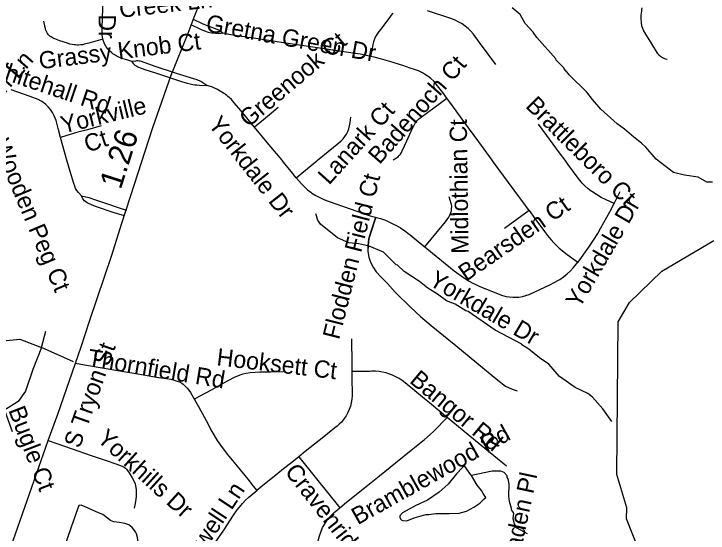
# Model space of a CAD drawing. Extents: x 1383679 to 1536984, y 460658 to 651027.
# Drawn here: x 1424590 to 1428413, y 515011 to 517873 of the extents above; entities that cross this region are included whole.
import ezdxf

# ---------------------------------------------------------------- set-up
doc = ezdxf.new("R2010")
doc.units = 0
for name, color, linetype in [('Exist Hydrographic Creek Single Shore', 7, 'Continuous'), ('Exist Hydrographic Misc Water Feature', 7, 'Continuous'), ('Exist Road Non-System Type 51', 7, 'Continuous'), ('Exist Road Non-System Type 51 Label', 7, 'Continuous'), ('Exist Road Primary NC Label', 7, 'Continuous'), ('Exist Road Primary NC Service Mileage Hundredths English Label', 7, 'Continuous'), ('Exist Road Primary NC UnDivided 4 Lane Attributed', 7, 'Continuous')]:
    doc.layers.add(name, color=color, linetype=linetype)

msp = doc.modelspace()

# ---------------------------------------------------------------- linework, layer by layer
at = {"layer": 'Exist Hydrographic Creek Single Shore'}
msp.add_lwpolyline([(1428455.5, 514657.5), (1428398.5, 514707.9), (1428207.5, 514728.2), (1428083.4, 514789.8), (1427964.5, 515090.9), (1427965.4, 515149.9), (1427910.5, 515334.8), (1427918.5, 516175), (1427979.5, 516282.1), (1428157.5, 516455.7), (1428444.5, 516623.9)], dxfattribs=at)
at = {"layer": 'Exist Hydrographic Misc Water Feature'}
for points in [[(1428438.2, 516945.2), (1428406.2, 516945.9), (1428358.9, 516973), (1428283.1, 516984.7), (1428223.3, 516998), (1428127, 517072.1), (1428070.4, 517137.4), (1428046.9, 517159.9), (1428003.5, 517192.9), (1427952.6, 517238), (1427913.1, 517266.9), (1427822.9, 517346.9), (1427776, 517399.9), (1427745.2, 517440.9), (1427648.9, 517534.7), (1427645.1, 517542.8), (1427619.7, 517569.3), (1427617.7, 517575.4), (1427576.7, 517618.3), (1427574.9, 517624.4), (1427469.4, 517742.7), (1427450, 517771.1), (1427405, 517820.1), (1427378.1, 517868.7), (1427334.8, 517905.6)], [(1427882.2, 515626.6), (1427833, 515695.4), (1427776.4, 515760.6), (1427750.9, 515781.2), (1427681.6, 515814.7), (1427594.9, 515874.6), (1427536.3, 515942), (1427483.9, 515977.1), (1427426.1, 516024.4), (1427386.6, 516049.2), (1427386.7, 516053.2), (1427240.3, 516130.5), (1427092.5, 516231.8), (1427078.6, 516236.1), (1427019.4, 516273.4), (1426971.8, 516290.5), (1426922.5, 516328.1), (1426869.3, 516360.8), (1426824.1, 516397.7), (1426739.3, 516453.7), (1426702, 516488.5), (1426696, 516490.6), (1426625.6, 516560.1), (1426546.2, 516591.9), (1426490.4, 516605.1), (1426434.6, 516610.4), (1426371.2, 516637.8), (1426278.8, 516713.9), (1426263.2, 516736.2), (1426252.1, 516770.5)], [(1427109.6, 515328.1), (1427107, 515331.9), (1427070.8, 515382.3), (1427059.9, 515372.9), (1427027.2, 515337.7), (1426981.8, 515280.7), (1426932.9, 515237.8), (1426867.9, 515193.3), (1426803.2, 515162.8), (1426730.4, 515122.4), (1426716.1, 515106.8), (1426715.8, 515096.8), (1426723.6, 515084.6), (1426731.5, 515080.4), (1426753.5, 515079.9), (1426793.8, 515095), (1426858.2, 515113.5), (1426874.2, 515113.2), (1426914.4, 515120.3), (1426986.4, 515118.7), (1427042.4, 515121.4), (1427082.7, 515132.5), (1427123.1, 515153.6), (1427155.6, 515176.9), (1427178.2, 515198.3), (1427189.3, 515208.4), (1427174.8, 515230.4), (1427165.2, 515246.6), (1427141.8, 515275.1), (1427109.6, 515328.1)], [(1427419.2, 515007.6), (1427360.7, 515038.3), (1427346.5, 515063.2), (1427338.7, 515089.6), (1427343, 515121.8), (1427330.8, 515138.9), (1427331.1, 515146.9), (1427319.9, 515185.2), (1427316.5, 515215.2), (1427317.9, 515279.2), (1427314.4, 515303.2), (1427306.8, 515319.4), (1427307, 515327.4), (1427289.3, 515345.8), (1427271.5, 515352.2), (1427223.5, 515353.2), (1427109.6, 515328.1)]]:
    msp.add_lwpolyline(points, dxfattribs=at)
at = {"layer": 'Exist Road Non-System Type 51'}
for p, q in [((1427895.7, 516827.7), (1427929.6, 516894.4)), ((1427427.3, 516789.1), (1427292.5, 516690.6))]:
    msp.add_line(p, q, dxfattribs=at)
for points in [[(1425080.1, 517733.5), (1425075.9, 517756.5), (1425075.3, 517761.1), (1425075.2, 517765.2), (1425075.3, 517768.6), (1425075.3, 517771.8), (1425075.6, 517796), (1425082.4, 517956.8), (1425085.6, 518010.6)], [(1426677.3, 517876), (1426668.2, 517865.7), (1426660.3, 517854.5), (1426659.2, 517852.8), (1426610.2, 517788.8), (1426598.8, 517774.7), (1426588.6, 517759.7), (1426579.8, 517743.8), (1426570.3, 517718.9), (1426567.2, 517702.9), (1426562.3, 517681.9), (1426553.3, 517638.5)], [(1427244.1, 517594.4), (1427153.5, 517715.5), (1427121.3, 517761.1), (1427107, 517776.8), (1427091.7, 517791.4), (1427075.2, 517804.8), (1427057.9, 517816.9), (1427039.6, 517827.7), (1427020.7, 517837.1), (1426995.9, 517846.9), (1426867.8, 517888.7)], [(1428048, 517906.5), (1428046.6, 517896.7), (1428045.6, 517887.6), (1428043.4, 517864.9), (1428042.7, 517848.3), (1428043.7, 517823), (1428046.5, 517807), (1428051.2, 517793), (1428057.3, 517779.5), (1428067.7, 517760.8), (1428101.8, 517707.1), (1428132.8, 517656.4), (1428141.4, 517647.1), (1428151.1, 517639), (1428161.7, 517632.2), (1428173.1, 517626.7), (1428185, 517622.7), (1428188.1, 517622)], [(1425080.1, 517733.5), (1425003.2, 517711.6), (1424992.9, 517708.6), (1424979.3, 517705), (1424968.1, 517702.7), (1424958.3, 517701.6), (1424946.3, 517700.9), (1424937.9, 517700.7), (1424929.9, 517701.3), (1424921.3, 517702), (1424911.2, 517703.6), (1424898.5, 517706.1), (1424884.4, 517710.7), (1424842.1, 517724.9), (1424814.6, 517735.6), (1424809.9, 517737.5), (1424806.3, 517739.1), (1424800.9, 517742.1), (1424794.6, 517746), (1424788.2, 517750.1), (1424784.5, 517753), (1424781.7, 517755.8), (1424778.4, 517759.5), (1424775.1, 517764.1), (1424773, 517767.7), (1424771.1, 517771.2), (1424769.1, 517775.2), (1424767.2, 517779.8), (1424764.8, 517786.8), (1424763.3, 517792.8), (1424762.3, 517797.8), (1424754.3, 517831.7)], [(1425578, 517842.8), (1425631.1, 517817.2), (1425662.8, 517805.2), (1425698.5, 517792.3), (1425720.1, 517782.2), (1425741.6, 517766.1)], [(1425741.6, 517766.1), (1425719.1, 517763.3), (1425700.7, 517763.6), (1425679, 517766.1), (1425662.1, 517770.4), (1425641.9, 517777.3), (1425619.5, 517787), (1425566.2, 517811.7)], [(1426553.3, 517638.5), (1426545.8, 517640.2), (1426507.9, 517648.4), (1426497.5, 517650.2), (1426380.8, 517667.1), (1426345.7, 517671.9), (1426249.8, 517686.6), (1426136.8, 517704.4), (1426075, 517713.8), (1426029.2, 517720.1), (1425946.4, 517732.9), (1425921.9, 517736.4), (1425896.6, 517740.3), (1425878.7, 517742.8), (1425860.7, 517745.8), (1425843.6, 517748.4), (1425818.8, 517751.8), (1425773.2, 517759.3), (1425741.6, 517766.1)], [(1425239.9, 517609.6), (1425211.5, 517618.5), (1425184.2, 517627.3), (1425164.9, 517635.6), (1425153.5, 517641.1), (1425141.7, 517648.5), (1425135, 517653.2), (1425129.3, 517657.4), (1425116, 517669.2), (1425098.2, 517690.2), (1425088.9, 517707.8), (1425080.1, 517733.5)], [(1425474, 517547.5), (1425367.6, 517583.5), (1425292.4, 517609.5), (1425286.2, 517611.2), (1425280.3, 517612.3), (1425272.3, 517612.9), (1425265.1, 517613.1), (1425259.4, 517612.7), (1425239.9, 517609.6)], [(1425239.9, 517609.6), (1425246.9, 517598.3), (1425251.7, 517592.7), (1425255.3, 517590.1), (1425259.8, 517587.4), (1425266.2, 517584), (1425271.9, 517581.3), (1425275.9, 517579.7), (1425311.4, 517566.9), (1425369.8, 517547), (1425463.3, 517515.7)], [(1426975, 517407.6), (1426951.3, 517439.7), (1426923.7, 517476.1), (1426902.1, 517501.4), (1426886.3, 517515.6), (1426869.5, 517528.6), (1426851.7, 517540.3), (1426840.4, 517546.8), (1426818.6, 517557.8), (1426796.9, 517565.7), (1426772, 517574.3), (1426731.2, 517587.8), (1426659.9, 517609.3), (1426609.4, 517624.3), (1426573.8, 517633.8), (1426553.3, 517638.5)], [(1425653.2, 517478.6), (1425618.9, 517499.7), (1425598.4, 517508.4), (1425519.4, 517532.2), (1425474, 517547.5)], [(1425463.3, 517515.7), (1425513.5, 517499.7), (1425543.3, 517491.4), (1425559.9, 517487.3), (1425568.2, 517485.3), (1425575.9, 517483.7), (1425585.6, 517482), (1425591.5, 517481.3), (1425597.8, 517480.8), (1425611.7, 517480), (1425653.2, 517478.6)], [(1424846.2, 517191.9), (1424834.8, 517234.2), (1424821.8, 517284.6), (1424812, 517309.9), (1424802.1, 517329.4), (1424791.9, 517345.6), (1424778.9, 517360.4), (1424766.4, 517373.7), (1424754.5, 517382.8), (1424740, 517392.2), (1424723.8, 517400.4), (1424680.1, 517417.2), (1424605.6, 517442.4), (1424574.1, 517453.3)], [(1425915.5, 517247.4), (1425913.2, 517250.1), (1425839.5, 517339.4), (1425803.6, 517383.3), (1425787.4, 517400.4), (1425776.1, 517411.2), (1425769, 517417.7), (1425762.2, 517423.3), (1425755.4, 517428.4), (1425751.1, 517431.6), (1425744.1, 517436.3), (1425726.4, 517447.5), (1425711.7, 517455.8), (1425703.7, 517459.7), (1425690.6, 517465.4), (1425680, 517469.7), (1425672.3, 517472.5), (1425653.2, 517478.6)], [(1426678.7, 517067.8), (1426706.1, 517085.4), (1426712.4, 517091.3), (1426719, 517099.5), (1426724, 517108.9), (1426728.3, 517118.5), (1426753.6, 517172.9), (1426784.8, 517242.2), (1426791.8, 517256.4), (1426800.2, 517269.8), (1426809.8, 517282.3), (1426820.7, 517293.8), (1426832.1, 517303.2), (1426938.4, 517380.4), (1426975, 517407.6)], [(1427427.3, 516789.1), (1427407.8, 516816.1), (1427313.5, 516943.8), (1427231.9, 517055.8), (1427224.4, 517066), (1427150.6, 517166.8), (1427073.6, 517271.9), (1427011.2, 517358.5), (1426975, 517407.6)], [(1426046, 517357.1), (1426008.4, 517325.5), (1425965.1, 517288.4), (1425915.5, 517247.4)], [(1426145, 516969.7), (1426258.3, 517062.8), (1426262.2, 517066), (1426378.9, 517162.2), (1426390.9, 517172), (1426402.4, 517183.5), (1426412.5, 517196.2), (1426421.2, 517209.8), (1426428.5, 517224.3), (1426434.1, 517239.2), (1426434.3, 517239.5), (1426438.5, 517256.4), (1426441.2, 517273.7), (1426441.2, 517274), (1426445.2, 517302.6)], [(1427895.7, 516827.7), (1427851.1, 516847.8), (1427824.4, 516861.5), (1427798.5, 516876.6), (1427773.4, 516893), (1427769.8, 516895.6), (1427752.3, 516908.9), (1427735.7, 516923.4), (1427720.3, 516939), (1427706, 516955.7), (1427697.1, 516967.6), (1427641.1, 517044.8), (1427625.5, 517066), (1427595.2, 517107.1), (1427525, 517202.7), (1427478.5, 517264.9)], [(1425071.2, 517255.2), (1424995.9, 517233.9), (1424941.4, 517220.2), (1424928.8, 517216.8), (1424922.5, 517215.1), (1424917.9, 517213.8), (1424912.4, 517212.2), (1424905.8, 517210.4), (1424846.2, 517191.9)], [(1426145, 516969.7), (1426117.5, 517003.5), (1426075, 517055.4), (1426066.6, 517066), (1425994.5, 517153.3), (1425915.5, 517247.4)], [(1424962.1, 516870.2), (1424945.5, 516887.8), (1424936.7, 516899), (1424929.9, 516910.2), (1424924.6, 516922.3), (1424919.9, 516937.5), (1424899.9, 517003.8), (1424881.6, 517066), (1424846.2, 517191.9)], [(1426145, 516969.7), (1426158.6, 516953.1), (1426173.7, 516935.5), (1426189.8, 516919.1), (1426206.9, 516903.8), (1426225.1, 516889.6), (1426230.9, 516885.5), (1426252.1, 516872.2), (1426274.1, 516860.3), (1426296.8, 516849.8), (1426320.3, 516840.5), (1426325.5, 516838.7), (1426442.1, 516798.4), (1426552.3, 516760), (1426608.1, 516745.9), (1426635.7, 516735.4), (1426662.5, 516723.7), (1426688.7, 516710.5), (1426693.1, 516708.1), (1426718.6, 516693.1), (1426743.3, 516676.9), (1426767.2, 516659.3), (1426771.8, 516655.6), (1426827.8, 516609.9), (1426853.4, 516588.9)], [(1424962.1, 516870.2), (1425001.9, 516861.2), (1425034.6, 516849.3), (1425100.7, 516827.5), (1425169.3, 516804.3), (1425210.1, 516791)], [(1425198.7, 516759.3), (1425141.9, 516776.1), (1425044.1, 516809.9), (1425021, 516817.9), (1424993.8, 516831), (1424978.5, 516842), (1424970.2, 516852.6), (1424962.1, 516870.2)], [(1426853.4, 516588.9), (1426922.7, 516673), (1426967.1, 516726.7), (1426976.8, 516739.3), (1426985.3, 516753.2), (1426992.4, 516767.9), (1426997.8, 516783.1), (1426999, 516787.2), (1427000.8, 516798.8), (1427000.9, 516810.5), (1426999.5, 516822.1), (1426998.1, 516828.3), (1426986.3, 516863.9)], [(1427696, 516503.7), (1427697.1, 516505.2), (1427756.5, 516588), (1427781.3, 516624.9), (1427804.9, 516662.7), (1427823, 516693.9), (1427872.7, 516782.2), (1427895.7, 516827.7)], [(1427427.3, 516789.1), (1427458.6, 516745.7), (1427511.8, 516674.2), (1427528.5, 516651.5), (1427546.4, 516629.7), (1427565.5, 516609), (1427585.8, 516589.4), (1427593.6, 516582.4), (1427636.2, 516547.4), (1427696, 516503.7)], [(1426583.5, 516752.1), (1426549.5, 516651.7), (1426545, 516633.4), (1426540.5, 516596.2), (1426539.5, 516562.8), (1426544.2, 516531.6), (1426553.9, 516505.2), (1426568.4, 516476.2), (1426585.1, 516451), (1426611.6, 516423.3), (1426647.8, 516386.1), (1426689.9, 516339.2), (1426776.4, 516255), (1426829.4, 516204.4), (1426888.2, 516156.3), (1427024.6, 516045.9), (1427255.1, 515854.4), (1427297.2, 515822), (1427333.4, 515803.9), (1427361, 515795.5)], [(1426541.6, 516561.9), (1426540.5, 516577.3), (1426540.5, 516596.1), (1426542, 516614.9), (1426545, 516633.4), (1426549.5, 516651.7), (1426555.5, 516669.8), (1426571, 516713.6), (1426583.5, 516752)], [(1426853.4, 516588.9), (1426896, 516554), (1427014.1, 516456.8), (1427039.6, 516437.4), (1427066.1, 516419.2), (1427093.5, 516402.4), (1427121.5, 516387), (1427127.1, 516384.2), (1427152.4, 516372.2), (1427178.4, 516361.7), (1427182.7, 516360.1), (1427281.7, 516321.2), (1427300.4, 516316.1), (1427319.4, 516312.7), (1427338.5, 516311), (1427357.7, 516311), (1427370.6, 516311.9), (1427390.1, 516315.3), (1427409, 516320.3), (1427427.3, 516326.8), (1427430.7, 516328.2), (1427514.4, 516365.9), (1427542.3, 516379.3), (1427569.4, 516394), (1427585.2, 516403.2), (1427595.7, 516409.6), (1427616.7, 516424.4), (1427636.4, 516440.3), (1427655.1, 516457.4), (1427672.7, 516475.6), (1427689.2, 516494.9), (1427696, 516503.7)], [(1424917.7, 515954.5), (1424741.1, 516033.9), (1424766.7, 516123.5)], [(1424439.2, 516077.4), (1424510.8, 516069.7), (1424623.4, 516080), (1424741.1, 516033.9)], [(1426449.6, 516081.9), (1426451.1, 515944.6), (1426451.4, 515902.6)], [(1424741.1, 516033.9), (1424695.1, 515913.5), (1424654.1, 515793.2), (1424613.2, 515736.9), (1424539, 515688.2), (1424579.9, 515570.5)], [(1424928.9, 515947.2), (1424979.5, 515937.9), (1425163.1, 515907.9), (1425272.1, 515889.9), (1425386.9, 515869.8), (1425388.6, 515869.6), (1425430.5, 515862.8), (1425455, 515859.2), (1425472.2, 515855.1), (1425489.6, 515849.4), (1425501.6, 515844.5), (1425514.7, 515837.1), (1425521.5, 515832.2), (1425528.8, 515825.7), (1425544.1, 515810.5), (1425553.6, 515798.6), (1425562.3, 515786.4), (1425606.5, 515709.8), (1425648.3, 515631.7), (1425680.9, 515571.5), (1425710.2, 515522.7), (1425728.1, 515495.8), (1425765.2, 515447), (1425818.8, 515380.3), (1425877.5, 515308.1), (1425907.6, 515270.5), (1425927.1, 515245.9)], [(1426072.5, 515899.3), (1426002.4, 515898.2), (1425972.1, 515898.3), (1425944.2, 515898), (1425918.6, 515897.2), (1425890.2, 515894.9), (1425868, 515890.6), (1425851.4, 515887), (1425834.3, 515881.5), (1425821.3, 515876.6), (1425806, 515870.1), (1425769, 515850.6), (1425728.3, 515828.4), (1425675.9, 515799.3), (1425609.7, 515764), (1425584.6, 515748.9)], [(1426451.4, 515902.6), (1426451.7, 515853.7), (1426452.5, 515788.5), (1426452.6, 515768.6), (1426451.2, 515749.1), (1426448.2, 515729.9), (1426443.8, 515710.7), (1426443.7, 515710.4), (1426437.2, 515692.5), (1426429.3, 515675.2), (1426420.1, 515658.5), (1426409.5, 515642.5), (1426405.1, 515636.6), (1426394, 515623.2), (1426381.9, 515610.9), (1426368.6, 515599.6), (1426366.6, 515598.1), (1426296.5, 515542.3), (1426194.9, 515460.5), (1426159.2, 515431.7)], [(1426975.6, 515648.7), (1426936.5, 515680.8), (1426877.9, 515728.7), (1426851.4, 515751.1), (1426744.5, 515839.5), (1426728.3, 515852), (1426711.3, 515863.2), (1426693.6, 515873), (1426675.2, 515881.6), (1426659.3, 515887.7), (1426640.1, 515893.8), (1426620.6, 515898.4), (1426600.8, 515901.6), (1426580.8, 515903.2), (1426560.6, 515903.4), (1426551.1, 515902.9), (1426451.4, 515902.6)], [(1426385.4, 515151.5), (1426421.7, 515181.1), (1426511.8, 515253.6), (1426602.7, 515326.8), (1426691.5, 515398.4), (1426786.4, 515475.1), (1426851, 515527.1), (1426882.2, 515554.4), (1426902.9, 515573.7), (1426975.6, 515648.7)], [(1427303.7, 515380.6), (1427184.4, 515477.2), (1427068.9, 515571.9), (1426975.6, 515648.7)], [(1424778.9, 515521.9), (1424820.5, 515506.8), (1424911.1, 515476.6), (1425016, 515439.4), (1425092.2, 515413.3), (1425156.4, 515391.6), (1425185.3, 515381), (1425198.1, 515375), (1425204.3, 515369.9), (1425209.7, 515364.2), (1425224.8, 515343), (1425241.1, 515316.1), (1425251.9, 515295.8), (1425257.1, 515283.7), (1425260.4, 515271.1), (1425262.8, 515251.8), (1425264.1, 515228.2), (1425263.5, 515215.8), (1425262.3, 515199), (1425257.8, 515174.9), (1425252.1, 515148.4)], [(1426159.2, 515431.7), (1426120.5, 515400.4), (1426075, 515364.9), (1426043.1, 515339.8), (1425950.4, 515265.4), (1425927.1, 515245.9)], [(1426159.2, 515431.7), (1426256.5, 515311), (1426316.7, 515235.9), (1426385.4, 515151.5)], [(1425667, 514909.7), (1425693.4, 514950.1), (1425745.2, 515028), (1425798.7, 515110.4), (1425820, 515139.1), (1425832.8, 515155.3), (1425848.5, 515173.9), (1425863.9, 515190.5), (1425884.4, 515210.3), (1425927.1, 515245.9)], [(1425274.6, 514963.2), (1425271.4, 514986.7), (1425265.6, 515006.9), (1425260, 515019), (1425240.6, 515042.4), (1425222.1, 515057.8), (1425201.1, 515065), (1425171.2, 515069.8), (1425140.6, 515073.9), (1425122, 515081.2), (1425105.1, 515094.1), (1425080, 515113.4), (1425056.6, 515123.9), (1424982.4, 515155.4), (1424959.8, 515165.9), (1424947.6, 515163.5), (1424939.6, 515144.1), (1424905.6, 515044.8), (1424883.9, 514979.4), (1424869.6, 514944), (1424861.2, 514901.2), (1424865.5, 514865.8), (1424870, 514828.6)], [(1426245.1, 514793.5), (1426250.2, 514838.4), (1426264.3, 514955.9), (1426267.9, 514976.7), (1426272.9, 514997.1), (1426279.5, 515017.1), (1426287.5, 515036.8), (1426289.7, 515041.7), (1426299.7, 515059.8), (1426310.8, 515077.2), (1426323.3, 515093.6), (1426336.9, 515109.2), (1426351.7, 515123.8), (1426353.7, 515125.7), (1426385.4, 515151.5)]]:
    msp.add_lwpolyline(points, dxfattribs=at)
at = {"layer": 'Exist Road Primary NC UnDivided 4 Lane Attributed'}
msp.add_lwpolyline([(1424263.4, 514052.6), (1424778.9, 515521.9), (1424831.4, 515666.8), (1424961.1, 516037.5), (1425008, 516184.9), (1425129.2, 516542.7), (1425182.9, 516714.4), (1425232.8, 516866.3), (1425354.5, 517247.1), (1425456.4, 517534.2), (1425548.8, 517765.4), (1425582.2, 517853.9), (1425618.1, 517943), (1425647.3, 518004.2), (1425719, 518136.2), (1425795.6, 518261), (1425870.7, 518361.5), (1425965.6, 518478), (1426075, 518589.2), (1426252.1, 518737.8), (1427466.3, 519638.3)], dxfattribs=at)

# ---------------------------------------------------------------- texts
at = {"layer": 'Exist Road Non-System Type 51 Label'}
for s, rotation, p in [('Creek Ln', 6.5606, (1425175.3, 517850.5)), ('Dr', 269.9996, (1425056.4, 517869.6)), ('Gretna Green Dr', 349.696, (1425642.5, 517777.3)), ('Grassy Knob Ct', 7.0914, (1424733.2, 517567.1)), ('Greenook Ct', 40.2218, (1425881.2, 517243.3)), ('Olde Whitehall Rd', 341.4471, (1424132.3, 517645.7)), ('Captain John Ln', 48.7963, (1424094.2, 516920.3)), ('Badenoch Ct', 48.7426, (1426603.3, 517038.7)), ('Brattleboro Ct', 315.1933, (1427403.3, 517360.5)), ('Yorkville', 13.6278, (1424860.9, 517213)), ('Lanark Ct', 48.0127, (1426325.3, 516925.9)), ('Yorkdale Dr', 308.1253, (1425655.8, 517262.5)), ('Midlothian Ct', 90.8053, (1427094.4, 516551.2)), ('Ct', 18.4358, (1424995, 517107.4)), ('Wooden Peg Ct', 292.7142, (1424471.6, 517159.2)), ('Flodden Field Ct', 75.8596, (1426380.9, 516073.6)), ('Bearsden Ct', 34.6863, (1427080.2, 516395.6)), ('Yorkdale Dr', 59.8591, (1427705, 516245.1)), ('Yorkdale Dr', 329.6346, (1426868.7, 516381.8)), ('Thornfield Rd', 350.5385, (1424991.6, 515933.3)), ('Hooksett Ct', 353.3195, (1425703.3, 515936.5)), ('Bangor Rd', 320.1948, (1426763.7, 515844.4)), ('Bugle Ct', 290.9998, (1424558, 515689.5)), ('Bramblewood Rd', 29.2791, (1426483.3, 515054.5)), ('Yorkhills Dr', 317.7389, (1425041.8, 515523.6)), ('Cravenridge Dr', 308.1508, (1426077.8, 515348.6)), ('Baden Pl', 77.9049, (1427365.3, 514830)), ('Cormwell Ln', 56.5079, (1425476.6, 514662.9))]:
    msp.add_text(s, height=95, rotation=rotation, dxfattribs=at).set_placement(p)
at = {"layer": 'Exist Road Primary NC Label'}
msp.add_text('S Tryon St', height=95, rotation=70.5546, dxfattribs=at).set_placement((1424952, 515474.1))
at = {"layer": 'Exist Road Primary NC Service Mileage Hundredths English Label'}
msp.add_text('1.26', height=125, rotation=72.2809, dxfattribs=at).set_placement((1425178.2, 516900.8))

doc.saveas('drawing.dxf')
